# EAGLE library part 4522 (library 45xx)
Prog. BCD divide by n COUNTER
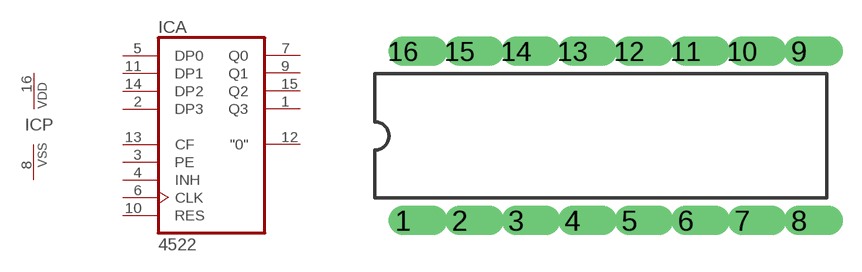
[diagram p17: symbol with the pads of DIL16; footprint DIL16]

Designator prefix IC; gates A=4522 P=PWRN

## 4522N  [DIL16]
1  A:Q3  out
2  A:DP3  in
3  A:PE  in
4  A:INH  in
5  A:DP0  in
6  A:CLK  in
7  A:Q0  out
8  P:VSS  pwr
9  A:Q1  out
10  A:RES  in
11  A:DP1  in
12  A:"0"  out
13  A:CF  in
14  A:DP2  in
15  A:Q2  out
16  P:VDD  pwr

## Footprint DIL16 (pad centres in mm)
Dual In Line
drill 0.813 offset: 1 -8.89,-3.81; 2 -6.35,-3.81; 3 -3.81,-3.81; 4 -1.27,-3.81; 5 1.27,-3.81; 6 3.81,-3.81; 7 6.35,-3.81; 8 8.89,-3.81; 9 8.89,3.81; 10 6.35,3.81; 11 3.81,3.81; 12 1.27,3.81; 13 -1.27,3.81; 14 -3.81,3.81; 15 -6.35,3.81; 16 -8.89,3.81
